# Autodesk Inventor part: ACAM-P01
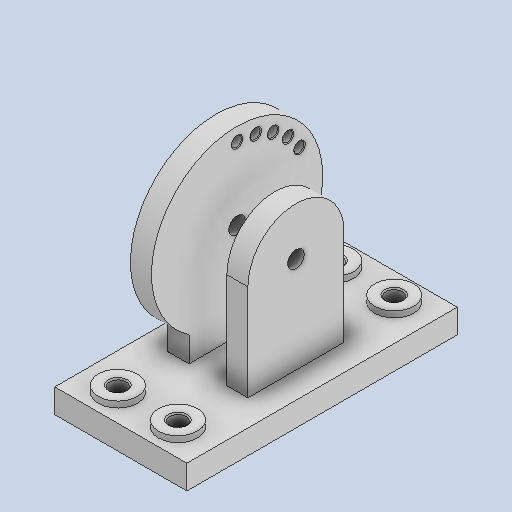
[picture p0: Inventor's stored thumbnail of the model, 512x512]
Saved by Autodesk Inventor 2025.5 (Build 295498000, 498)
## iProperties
Company: Open CASCADE
Created: 2026-10
Part Number: ACAM-P01
Material: Genérico
Description: Horquilla de cámara
Document SubType Name: Modeling
Designer: Luis M
Authority: Unknown
Density: 1 g/cm^3
Appearance: Valor por defecto
Sending System: Open CASCADE 7.9
Preprocessor: Open CASCADE STEP processor 7.9
Material_BOM: PLA
Proceso_BOM: Impresión 3D
Title: Open CASCADE Shape Model
Author: Author
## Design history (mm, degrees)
feature "Base1"
node "Sólido1"
